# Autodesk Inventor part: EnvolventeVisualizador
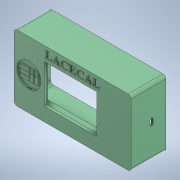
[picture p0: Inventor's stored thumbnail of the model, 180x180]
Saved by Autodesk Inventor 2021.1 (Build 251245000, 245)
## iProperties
Created: 2021-06
Part Number: EnvolventeVisualizador
Material: Genérico
Document SubType Name: Modeling
Designer: Ricardo
Density: 1 g/cm^3
Appearance: Valor por defecto
Author: Ricardo
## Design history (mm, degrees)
sketch "Boceto1"
  geometry: L1 (-74, -40.5)-(74, -40.5); L2 (74, -40.5)-(74, 40.5); L3 (74, 40.5)-(-74, 40.5); L4 (-74, 40.5)-(-74, -40.5); L5 (-74, -40.5)-(74, 40.5); L6 (74, -40.5)-(-74, 40.5); L7 (-75, 41.5)-(75, 41.5); L8 (75, 41.5)-(75, -41.5); L9 (75, -41.5)-(-75, -41.5); L10 (-75, -41.5)-(-75, 41.5); L11 (70, -35)-(-70, -35); L12 (-70, -35)-(-70, 35); L13 (-70, 35)-(70, 35); L14 (70, 35)-(70, -35); L15 (70, -35)-(-70, 35); L16 (-70, -35)-(70, 35); L17 (45, -28)-(-45, -28); L18 (-45, -28)-(-45, 28); L19 (-45, 28)-(45, 28); L20 (45, 28)-(45, -28); L21 (45, -28)-(-45, 28); L22 (-45, -28)-(45, 28); L23 (77.2, 43.7)-(-77.2, 43.7); L24 (-77.2, 43.7)-(-77.2, -43.7); L25 (-77.2, -43.7)-(77.2, -43.7); L26 (77.2, -43.7)-(77.2, 43.7); C1 r 2 at (-70, 35); C2 r 2 at (-70, -35); C3 r 2 at (70, -35); C4 r 2 at (70, 35); 1 further point
  constraints: 52 end point, 10 parallel, 6 midpoint, 5 perpendicular, 4 centre point, 4 coincident, 3 horizontal, 6 other
  dimensions: "d0" = 148 distance of L3.end L2.end; "d1" = 81 distance of L2.end L1.end; "d2" = 1 distance between parallel lines of L3 L7; "d3" = 140 distance of L12.end L13.end; "d4" = 70 distance of L11.end L12.end; "d5" = 90 distance of L18.end L19.end; "d6" = 56 distance of L17.end L18.end; "d7" = 4 diameter of C1; "d8" = 4 diameter of C2; "d9" = 4 diameter of C3; "d10" = 4 diameter of C4; "d11" = 2.2 distance between parallel lines of L7 L23
extrude "Extrusión1" new body sketch "Boceto1" distance "d12" = 3; taper "d13" = 0 deg
extrude "Extrusión2" join sketch "Boceto1" distance "d14" = 36; taper "d15" = 0 deg
sketch "Boceto2"
  geometry: L1 (-74, 40.5)-(74, 40.5) reference; L2 (-74, -40.5)-(-74, 40.5) reference; L3 (75, 41.5)-(-75, 41.5) reference; L4 (-65, 28.5)-(-75, 28.5); L5 (-75, 28.5)-(-75, 41.5); L6 (-75, 41.5)-(-65, 41.5); L7 (-65, 41.5)-(-65, 28.5); L8 (-65, 28.5)-(-75, 41.5); L9 (-75, 28.5)-(-65, 41.5); L10 (-75, 41.5)-(-75, -41.5) reference; L11 (-75, -41.5)-(75, -41.5) reference; L12 (-75, -41.5)-(75, -41.5) reference; L13 (-65, -28.5)-(-75, -28.5); L14 (-75, -28.5)-(-75, -41.5); L15 (-75, -41.5)-(-65, -41.5); L16 (-65, -41.5)-(-65, -28.5); L17 (-65, -28.5)-(-75, -41.5); L18 (-75, -28.5)-(-65, -41.5); L19 (75, -41.5)-(75, 41.5) reference; L20 (65, -28.5)-(75, -28.5); L21 (75, -28.5)-(75, -41.5); L22 (75, -41.5)-(65, -41.5); L23 (65, -41.5)-(65, -28.5); L24 (65, -28.5)-(75, -41.5); L25 (75, -28.5)-(65, -41.5); L26 (75, -41.5)-(75, 41.5) reference; L27 (65, 28.5)-(75, 28.5); L28 (75, 28.5)-(75, 41.5); L29 (75, 41.5)-(65, 41.5); L30 (65, 41.5)-(65, 28.5); L31 (65, 28.5)-(75, 41.5); L32 (75, 28.5)-(65, 41.5); C1 r 2 at (-70, 35) reference; C2 r 2 at (-70, -35) reference; C3 r 2 at (70, -35) reference; C4 r 2 at (70, 35) reference; 8 further points
  constraints: 48 end point, 8 midpoint, 8 parallel, 4 horizontal, 4 perpendicular
extrude "Extrusión3" join sketch "Boceto2" distance "d16" = 17; taper "d17" = 0 deg
sketch "Boceto3"
  geometry: L1 (-45, 28)-(-45, -28) reference; L2 (45, 28)-(-45, 28) reference; L3 (-45, -28)-(45, -28) reference; L4 (45, -28)-(45, 28) reference; L5 (-45, 28)-(-45, -28); L6 (-45, -28)-(-32, -28); L7 (-32, -28)-(-32, 28); L8 (-32, 28)-(-45, 28); L9 (45, 28)-(45, -28); L10 (45, -28)-(37, -28); L11 (37, -28)-(37, 28); L12 (37, 28)-(45, 28); L13 (-45, 28)-(45, 28); L14 (45, 28)-(45, 25.5); L15 (45, 25.5)-(-45, 25.5); L16 (-45, 25.5)-(-45, 28); L17 (-45, -28)-(45, -28); L18 (45, -28)-(45, -25.5); L19 (45, -25.5)-(-45, -25.5); L20 (-45, -25.5)-(-45, -28); L21 (-47, -30)-(-47, 30); L22 (-47, 30)-(47, 30); L23 (47, 30)-(47, -30); L24 (47, -30)-(-47, -30); 5 further points
  constraints: 40 end point, 8 parallel, 4 perpendicular, 3 collinear, 1 vertical, 3 other
  dimensions: "d18" = 13 distance of L6.end L1.end; "d19" = 8 distance of L3.end L10.end; "d20" = 2.5 distance of L2.start L14.end; "d21" = 2.5 distance of L18.end L3.end; "d22" = 2 distance between parallel lines of L1 L21
extrude "Extrusión5" join sketch "Boceto3" stored distance "d25" = 5; taper "d26" = 0 deg
fillet "Empalme1" dims "d27" = 10
sketch "Boceto4"
  geometry: L1 (20, 72.2)-(20, 85.2) reference; L2 (20, 2.2)-(20, 15.2) reference; L3 (20, 85.2)-(20, 2.2); L4 (39, 0)-(39, 87.4) reference; L5 (20, 2.2)-(20, 5.2) reference; L6 (20, 2.2)-(20, 0); L7 (39, 0)-(0, 0) reference; L8 (20, 85.2)-(20, 82.2) reference; L9 (20, 85.2)-(20, 90.116); L10 (20, 43.7)-(39, 43.7); L11 (27, 41.2)-(27, 46.2); L12 (27, 46.2)-(27, 41.2); L13 (25, 46.2)-(25, 41.2); L14 (29, 41.2)-(29, 46.2); A1 r 2 centre (27, 46.2) between (29, 46.2) and (25, 46.2); A2 r 2 centre (27, 41.2) between (25, 41.2) and (29, 41.2); 3 further points
  constraints: 18 end point, 4 midpoint, 4 point on circle, 4 tangent, 3 point on line, 2 centre point, 2 parallel, 2 vertical, 1 collinear
  dimensions: "d28" = 7 distance of point (27, 43.7) L10.start; "d29" = 5 distance of L11.start L11.end; "d30" = 4 diameter of A2
fillet "Empalme2" dims "d31" = 4
fillet "Empalme3" dims "d34" = 4
extrude "Extrusión6" cut sketch "Boceto4" stored distance "d32" = 5; taper "d33" = 0 deg
sketch "Boceto6"
  geometry: L1 (32, -25.5)-(32, 25.5) reference; L2 (-37, -25.5)-(32, -25.5) reference; L3 (-37, 25.5)-(-37, -25.5) reference; L4 (32, 25.5)-(-37, 25.5) reference; L5 (-77.187, 43.807)-(77.213, 43.593); L6 (77.213, 43.593)-(77.187, 25.393); L7 (77.187, 25.393)-(-77.213, 25.607); L8 (-77.213, 25.607)-(-77.187, 43.807); L9 (32, 25.5)-(-37, 25.5) reference; L10 (-57.259, 5.358)-(-57.259, 3.333); L11 (-57.259, 3.333)-(-63.309, 3.333); L12 (-63.309, 3.333)-(-69.359, 3.333); L13 (-69.359, 3.333)-(-69.359, 5.358); L14 (-69.359, 5.358)-(-69.359, 7.383); L15 (-69.359, 7.383)-(-63.309, 7.383); L16 (-63.309, 7.383)-(-57.259, 7.383); L17 (-57.259, 7.383)-(-57.259, 5.358); L18 (-51.459, 5.358)-(-51.459, 3.333); L19 (-51.459, 3.333)-(-53.759, 3.333); L20 (-53.759, 3.333)-(-56.059, 3.333); L21 (-56.059, 3.333)-(-56.059, 5.358); L22 (-56.059, 5.358)-(-56.059, 7.383); L23 (-56.059, 7.383)-(-53.759, 7.383); L24 (-53.759, 7.383)-(-51.459, 7.383); L25 (-51.459, 7.383)-(-51.459, 5.358); L26 (-45.659, 5.358)-(-45.659, 3.333); L27 (-45.659, 3.333)-(-47.959, 3.333); L28 (-47.959, 3.333)-(-50.259, 3.333); L29 (-50.259, 3.333)-(-50.259, 5.358); L30 (-50.259, 5.358)-(-50.259, 7.383); L31 (-50.259, 7.383)-(-47.959, 7.383); L32 (-47.959, 7.383)-(-45.659, 7.383); L33 (-45.659, 7.383)-(-45.659, 5.358); L34 (-57.259, 0.158)-(-57.259, -1.867); L35 (-57.259, -1.867)-(-63.309, -1.867); L36 (-63.309, -1.867)-(-69.359, -1.867); L37 (-69.359, -1.867)-(-69.359, 0.158); L38 (-69.359, 0.158)-(-69.359, 2.183); L39 (-69.359, 2.183)-(-63.309, 2.183); L40 (-63.309, 2.183)-(-57.259, 2.183); L41 (-57.259, 2.183)-(-57.259, 0.158); L42 (-51.459, -2.517)-(-51.459, -7.217); L43 (-51.459, -7.217)-(-53.759, -7.217); L44 (-53.759, -7.217)-(-56.059, -7.217); L45 (-56.059, -7.217)-(-56.059, -2.517); L46 (-56.059, -2.517)-(-56.059, 2.183); L47 (-56.059, 2.183)-(-53.759, 2.183); L48 (-53.759, 2.183)-(-51.459, 2.183); L49 (-51.459, 2.183)-(-51.459, -2.517); L50 (-45.659, -2.517)-(-45.659, -7.217); L51 (-45.659, -7.217)-(-47.959, -7.217); L52 (-47.959, -7.217)-(-50.259, -7.217); L53 (-50.259, -7.217)-(-50.259, -2.517); L54 (-50.259, -2.517)-(-50.259, 2.183); L55 (-50.259, 2.183)-(-47.959, 2.183); L56 (-47.959, 2.183)-(-45.659, 2.183); L57 (-45.659, 2.183)-(-45.659, -2.517); L58 (-57.259, -5.142)-(-57.259, -7.217); L59 (-57.259, -7.217)-(-63.309, -7.217); L60 (-63.309, -7.217)-(-69.359, -7.217); L61 (-69.359, -7.217)-(-69.359, -5.142); L62 (-69.359, -5.142)-(-69.359, -3.067); L63 (-69.359, -3.067)-(-63.309, -3.067); L64 (-63.309, -3.067)-(-57.259, -3.067)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; A1 r 16.079 centre (-57.459, -0.166) between (-58.109, 15.9) and (-62.885, 14.97); A2 r 15.75 centre (-57.57, 0.144) between (-62.885, 14.97) and (-67.136, 12.656); A3 r 15.747 centre (-57.571, 0.146) between (-67.136, 12.656) and (-70.483, 9.16); A4 r 16.07 centre (-57.307, -0.039) between (-70.483, 9.16) and (-72.632, 4.796); A5 r 15.052 centre (-58.277, 0.267) between (-72.632, 4.796) and (-73.259, 1.72); A6 r 16.425 centre (-56.911, 0.135) between (-73.259, 1.72) and (-73.256, -1.488); A7 r 16.4 centre (-56.936, 0.132) between (-73.256, -1.488) and (-72.629, -4.632); A8 r 14.941 centre (-58.332, -0.292) between (-72.629, -4.632) and (-71.41, -7.517); A9 r 16.017 centre (-57.39, 0.229) between (-71.41, -7.517) and (-69.35, -10.425); A10 r 16.009 centre (-57.396, 0.223) between (-69.35, -10.425) and (-66.699, -12.805); A11 r 15.892 centre (-57.464, 0.128) between (-66.699, -12.805) and (-63.597, -14.533); A12 r 15.505 centre (-57.613, -0.229) between (-63.597, -14.533) and (-60.209, -15.515); A13 r 17.208 centre (-57.328, 1.45) between (-60.209, -15.515) and (-59.538, -15.616); A14 r 12.215 centre (-57.97, -3.501) between (-59.538, -15.616) and (-58.92, -15.68); A15 r 13.497 centre (-57.87, -2.224) between (-58.92, -15.68) and (-58.271, -15.715); A16 r 25.644 centre (-57.509, 9.918) between (-58.271, -15.715) and (-57.509, -15.726); A17 r 25.644 centre (-57.509, 9.918) between (-57.509, -15.726) and (-56.746, -15.715); A18 r 13.497 centre (-57.147, -2.224) between (-56.746, -15.715) and (-56.097, -15.68); A19 r 12.215 centre (-57.048, -3.501) between (-56.097, -15.68) and (-55.479, -15.616); A20 r 17.208 centre (-57.689, 1.45) between (-55.479, -15.616) and (-54.809, -15.515); A21 r 15.56 centre (-57.413, -0.174) between (-54.809, -15.515) and (-51.71, -14.652); A22 r 15.79 centre (-57.497, 0.039) between (-51.71, -14.652) and (-48.843, -13.168); A23 r 15.874 centre (-57.543, 0.11) between (-48.843, -13.168) and (-46.33, -11.127); A24 r 15.939 centre (-57.589, 0.156) between (-46.33, -11.127) and (-44.281, -8.617); A25 r 20.56 centre (-61.447, 2.699) between (-44.281, -8.617) and (-43.83, -7.901); A26 r 13.045 centre (-55.008, -1.175) between (-43.83, -7.901) and (-43.46, -7.243); A27 r 12.715 centre (-54.716, -1.329) between (-43.46, -7.243) and (-43.132, -6.572); A28 r 18.511 centre (-59.996, 1.061) between (-43.132, -6.572) and (-42.81, -5.817); A29 r 15.753 centre (-57.435, 0.036) between (-42.81, -5.817) and (-41.884, -2.475); A30 r 16.059 centre (-57.738, 0.085) between (-41.884, -2.475) and (-41.705, 1.006); A31 r 16.003 centre (-57.681, 0.088) between (-41.705, 1.006) and (-42.281, 4.437); A32 r 15.506 centre (-57.204, 0.223) between (-42.281, 4.437) and (-43.583, 7.634); A33 r 15.775 centre (-57.44, 0.094) between (-43.583, 7.634) and (-45.63, 10.553); A34 r 15.999 centre (-57.607, -0.054) between (-45.63, 10.553) and (-48.286, 12.949); A35 r 15.94 centre (-57.573, -0.006) between (-48.286, 12.949) and (-51.403, 14.691); A36 r 15.52 centre (-57.411, 0.381) between (-51.403, 14.691) and (-54.809, 15.682); A37 r 12.803 centre (-56.955, 3.06) between (-54.809, 15.682) and (-55.582, 15.789); A38 r 21.426 centre (-57.88, -5.513) between (-55.582, 15.789) and (-56.467, 15.866); A39 r 21.199 centre (-57.865, -5.287) between (-56.467, 15.866) and (-57.348, 15.906); A40 r 11.738 centre (-57.634, 4.172) between (-57.348, 15.906) and (-58.109, 15.9); A41 r 4 centre (73.2, 39.7) between (77.2, 39.7) and (73.2, 43.7) reference; A42 r 4 centre (-73.2, 39.7) between (-73.2, 43.7) and (-77.2, 39.7) reference; A43 r 4 centre (-73.2, -39.7) between (-77.2, -39.7) and (-73.2, -43.7) reference; A44 r 4 centre (73.2, -39.7) between (73.2, -43.7) and (77.2, -39.7) reference; 103 further points
  constraints: 112 end point, 80 point on circle, 40 centre point, 4 midpoint, 4 point on line, 2 other
extrude "Extrusión8" cut sketch "Boceto6" distance "d38" = 2; taper "d39" = 0 deg
sketch "Boceto8"
  geometry: L1 (-71, 41.5)-(71, 41.5) reference; L2 (-75, -37.5)-(-75, 37.5) reference; L3 (71, -41.5)-(-71, -41.5) reference; L4 (75, 37.5)-(75, -37.5) reference; C1 r 2 at (70, -35) reference; C2 r 2 at (70, 35) reference; C3 r 2 at (-70, 35) reference; C4 r 2 at (-70, -35) reference; A1 r 4 centre (-71, 37.5) between (-71, 41.5) and (-75, 37.5) reference; A2 r 4 centre (-71, -37.5) between (-75, -37.5) and (-71, -41.5) reference; A3 r 4 centre (71, -37.5) between (71, -41.5) and (75, -37.5) reference; A4 r 4 centre (71, 37.5) between (75, 37.5) and (71, 41.5) reference; 1 further point
sketch "Boceto9"
  geometry: L1 (-47, -30)-(-47, 30) reference; L2 (-47, 30)-(47, 30) reference; L3 (47, -30)-(-47, -30) reference; L4 (47, 30)-(47, -30) reference; L5 (48, 31)-(-48, 31); L6 (-48, 31)-(-48, -31); L7 (-48, -31)-(48, -31); L8 (48, -31)-(48, 31); L9 (46, 29)-(-46, 29); L10 (-46, 29)-(-46, -29); L11 (-46, -29)-(46, -29); L12 (46, -29)-(46, 29); 1 further point
  constraints: 16 end point, 6 other
  dimensions: "d40" = 1 distance between parallel lines of L2 L5; "d43" = 1 distance between parallel lines of L2 L9
extrude "Extrusión9" join sketch "Boceto9" distance "d41" = 10; taper "d42" = 0 deg
sketch "Boceto10"
  geometry: L1 (-77.2, 39.7)-(-77.2, -39.7) reference; L2 (-73.2, -43.7)-(73.2, -43.7) reference; L3 (77.2, -39.7)-(77.2, 39.7) reference; L4 (73.2, 43.7)-(-73.2, 43.7) reference; L5 (-71, 41.5)-(71, 41.5) reference; L6 (75, 37.5)-(75, -37.5) reference; L7 (71, -41.5)-(-71, -41.5) reference; L8 (-75, -37.5)-(-75, 37.5) reference; A1 r 4 centre (-73.2, 39.7) between (-73.2, 43.7) and (-77.2, 39.7) reference; A2 r 4 centre (-73.2, -39.7) between (-77.2, -39.7) and (-73.2, -43.7) reference; A3 r 4 centre (73.2, -39.7) between (73.2, -43.7) and (77.2, -39.7) reference; A4 r 4 centre (73.2, 39.7) between (77.2, 39.7) and (73.2, 43.7) reference; A5 r 4 centre (71, 37.5) between (75, 37.5) and (71, 41.5) reference; A6 r 4 centre (71, -37.5) between (71, -41.5) and (75, -37.5) reference; A7 r 4 centre (-71, -37.5) between (-75, -37.5) and (-71, -41.5) reference; A8 r 4 centre (-71, 37.5) between (-71, 41.5) and (-75, 37.5) reference; 1 further point
extrude "Extrusión10" join sketch "Boceto10" distance "d44" = 7; taper "d45" = 0 deg
node "Sólido1"
node "Contorno proyectado2"
node "Contorno proyectado3"
node "Contorno proyectado4"
